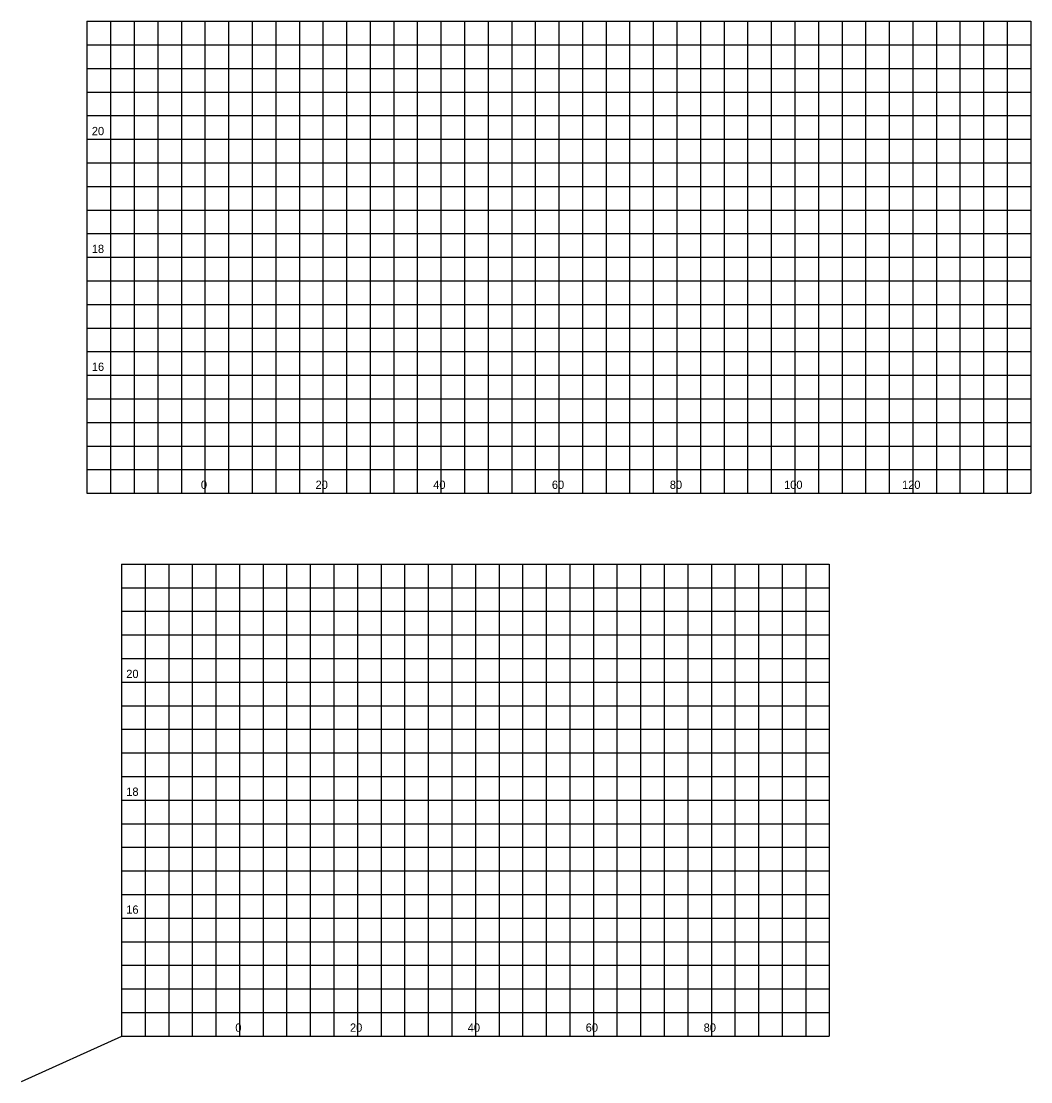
# Model space of a CAD drawing. Extents: x 127723 to 128378, y 21426 to 23736.
# Drawn here: x 128066.4 to 128237.5, y 21431.2 to 21611 of the extents above; entities that cross this region are included whole.
import ezdxf

# ---------------------------------------------------------------- set-up
doc = ezdxf.new("R2010")
doc.units = 0
for name, color, linetype in [('GroundCover', 7, 'Continuous'), ('Miscellaneous0', 7, 'Continuous'), ('SheetBorder_dp', 7, 'Continuous'), ('TextNotes', 7, 'Continuous')]:
    doc.layers.add(name, color=color, linetype=linetype)

msp = doc.modelspace()

# ---------------------------------------------------------------- linework, layer by layer
at = {"layer": 'Miscellaneous0'}
for p, q in [((128081.53, 21610.98), (128081.53, 21530.98)), ((128085.53, 21610.98), (128085.53, 21530.98)), ((128089.53, 21610.98), (128089.53, 21530.98)), ((128093.53, 21610.98), (128093.53, 21530.98)), ((128101.53, 21610.98), (128101.53, 21530.98)), ((128105.53, 21610.98), (128105.53, 21530.98)), ((128109.53, 21610.98), (128109.53, 21530.98)), ((128113.53, 21610.98), (128113.53, 21530.98)), ((128121.53, 21610.98), (128121.53, 21530.98)), ((128125.53, 21610.98), (128125.53, 21530.98)), ((128129.53, 21610.98), (128129.53, 21530.98)), ((128133.53, 21610.98), (128133.53, 21530.98)), ((128141.53, 21610.98), (128141.53, 21530.98)), ((128145.53, 21610.98), (128145.53, 21530.98)), ((128149.53, 21610.98), (128149.53, 21530.98)), ((128153.53, 21610.98), (128153.53, 21530.98)), ((128161.53, 21610.98), (128161.53, 21530.98)), ((128165.53, 21610.98), (128165.53, 21530.98)), ((128169.53, 21610.98), (128169.53, 21530.98)), ((128173.53, 21610.98), (128173.53, 21530.98)), ((128181.53, 21610.98), (128181.53, 21530.98)), ((128185.53, 21610.98), (128185.53, 21530.98)), ((128189.53, 21610.98), (128189.53, 21530.98)), ((128193.53, 21610.98), (128193.53, 21530.98)), ((128201.53, 21610.98), (128201.53, 21530.98)), ((128205.53, 21610.98), (128205.53, 21530.98)), ((128209.53, 21610.98), (128209.53, 21530.98)), ((128213.53, 21610.98), (128213.53, 21530.98)), ((128221.53, 21610.98), (128221.53, 21530.98)), ((128225.53, 21610.98), (128225.53, 21530.98)), ((128229.53, 21610.98), (128229.53, 21530.98)), ((128233.53, 21610.98), (128233.53, 21530.98)), ((128077.53, 21606.98), (128157.53, 21606.98)), ((128157.53, 21606.98), (128237.53, 21606.98)), ((128077.53, 21602.98), (128157.53, 21602.98)), ((128157.53, 21602.98), (128237.53, 21602.98)), ((128077.53, 21598.98), (128157.53, 21598.98)), ((128157.53, 21598.98), (128237.53, 21598.98)), ((128077.53, 21594.98), (128157.53, 21594.98)), ((128157.53, 21594.98), (128237.53, 21594.98)), ((128077.53, 21586.98), (128157.53, 21586.98)), ((128157.53, 21586.98), (128237.53, 21586.98)), ((128077.53, 21582.98), (128157.53, 21582.98)), ((128157.53, 21582.98), (128237.53, 21582.98)), ((128077.53, 21578.98), (128157.53, 21578.98)), ((128157.53, 21578.98), (128237.53, 21578.98)), ((128077.53, 21574.98), (128157.53, 21574.98)), ((128157.53, 21574.98), (128237.53, 21574.98)), ((128077.53, 21566.98), (128157.53, 21566.98)), ((128157.53, 21566.98), (128237.53, 21566.98)), ((128077.53, 21562.98), (128157.53, 21562.98)), ((128157.53, 21562.98), (128237.53, 21562.98)), ((128077.53, 21558.98), (128157.53, 21558.98)), ((128157.53, 21558.98), (128237.53, 21558.98)), ((128077.53, 21554.98), (128157.53, 21554.98)), ((128157.53, 21554.98), (128237.53, 21554.98)), ((128077.53, 21546.98), (128157.53, 21546.98)), ((128157.53, 21546.98), (128237.53, 21546.98)), ((128077.53, 21542.98), (128157.53, 21542.98)), ((128157.53, 21542.98), (128237.53, 21542.98)), ((128077.53, 21538.98), (128157.53, 21538.98)), ((128157.53, 21538.98), (128237.53, 21538.98)), ((128077.53, 21534.98), (128157.53, 21534.98)), ((128157.53, 21534.98), (128237.53, 21534.98)), ((128087.38, 21518.98), (128087.38, 21438.98)), ((128091.38, 21518.98), (128091.38, 21438.98)), ((128095.38, 21518.98), (128095.38, 21438.98)), ((128099.38, 21518.98), (128099.38, 21438.98)), ((128107.38, 21518.98), (128107.38, 21438.98)), ((128111.38, 21518.98), (128111.38, 21438.98)), ((128115.38, 21518.98), (128115.38, 21438.98)), ((128119.38, 21518.98), (128119.38, 21438.98)), ((128127.38, 21518.98), (128127.38, 21438.98)), ((128131.38, 21518.98), (128131.38, 21438.98)), ((128135.38, 21518.98), (128135.38, 21438.98)), ((128139.38, 21518.98), (128139.38, 21438.98)), ((128147.38, 21518.98), (128147.38, 21438.98)), ((128151.38, 21518.98), (128151.38, 21438.98)), ((128155.38, 21518.98), (128155.38, 21438.98)), ((128159.38, 21518.98), (128159.38, 21438.98)), ((128167.38, 21518.98), (128167.38, 21438.98)), ((128171.38, 21518.98), (128171.38, 21438.98)), ((128175.38, 21518.98), (128175.38, 21438.98)), ((128179.38, 21518.98), (128179.38, 21438.98)), ((128187.38, 21518.98), (128187.38, 21438.98)), ((128191.38, 21518.98), (128191.38, 21438.98)), ((128195.38, 21518.98), (128195.38, 21438.98)), ((128199.38, 21518.98), (128199.38, 21438.98)), ((128083.38, 21514.98), (128203.38, 21514.98)), ((128083.38, 21510.98), (128203.38, 21510.98)), ((128083.38, 21506.98), (128203.38, 21506.98)), ((128083.38, 21502.98), (128203.38, 21502.98)), ((128083.38, 21494.98), (128203.38, 21494.98)), ((128083.38, 21490.98), (128203.38, 21490.98)), ((128083.38, 21486.98), (128203.38, 21486.98)), ((128083.38, 21482.98), (128203.38, 21482.98)), ((128083.38, 21474.98), (128203.38, 21474.98)), ((128083.38, 21470.98), (128203.38, 21470.98)), ((128083.38, 21466.98), (128203.38, 21466.98)), ((128083.38, 21462.98), (128203.38, 21462.98)), ((128083.38, 21454.98), (128203.38, 21454.98)), ((128083.38, 21450.98), (128203.38, 21450.98)), ((128083.38, 21446.98), (128203.38, 21446.98)), ((128083.38, 21442.98), (128203.38, 21442.98))]:
    msp.add_line(p, q, dxfattribs=at)
at = {"layer": 'SheetBorder_dp'}
for p, q in [((128077.53, 21610.98), (128157.53, 21610.98)), ((128077.53, 21610.98), (128077.53, 21530.98)), ((128097.53, 21610.98), (128097.53, 21550.98)), ((128097.53, 21610.98), (128097.53, 21530.98)), ((128117.53, 21610.98), (128117.53, 21530.98)), ((128137.53, 21610.98), (128137.53, 21530.98)), ((128157.53, 21610.98), (128157.53, 21530.98)), ((128157.53, 21610.98), (128237.53, 21610.98)), ((128177.53, 21610.98), (128177.53, 21550.98)), ((128177.53, 21610.98), (128177.53, 21530.98)), ((128197.53, 21610.98), (128197.53, 21530.98)), ((128217.53, 21610.98), (128217.53, 21530.98)), ((128237.53, 21610.98), (128237.53, 21530.98)), ((128077.53, 21590.98), (128157.53, 21590.98)), ((128157.53, 21590.98), (128237.53, 21590.98)), ((128077.53, 21570.98), (128157.53, 21570.98)), ((128157.53, 21570.98), (128237.53, 21570.98)), ((128077.53, 21550.98), (128157.53, 21550.98)), ((128077.53, 21550.98), (128157.53, 21550.98)), ((128157.53, 21550.98), (128237.53, 21550.98)), ((128157.53, 21550.98), (128237.53, 21550.98)), ((128077.53, 21530.98), (128157.53, 21530.98)), ((128157.53, 21530.98), (128237.53, 21530.98)), ((128083.38, 21518.98), (128203.38, 21518.98)), ((128083.38, 21518.98), (128083.38, 21438.98)), ((128103.38, 21518.98), (128103.38, 21458.98)), ((128103.38, 21518.98), (128103.38, 21438.98)), ((128123.38, 21518.98), (128123.38, 21438.98)), ((128143.38, 21518.98), (128143.38, 21438.98)), ((128163.38, 21518.98), (128163.38, 21438.98)), ((128183.38, 21518.98), (128183.38, 21438.98)), ((128203.38, 21518.98), (128203.38, 21438.98)), ((128083.38, 21498.98), (128203.38, 21498.98)), ((128083.38, 21478.98), (128203.38, 21478.98)), ((128083.38, 21458.98), (128163.38, 21458.98)), ((128083.38, 21458.98), (128203.38, 21458.98)), ((128083.38, 21438.98), (128203.38, 21438.98))]:
    msp.add_line(p, q, dxfattribs=at)
at = {"layer": 'TextNotes'}
msp.add_line((128083.38, 21438.9), (128066.38, 21431.24), dxfattribs=at)

# ---------------------------------------------------------------- texts
at = {"layer": 'GroundCover'}
for s, p in [('20', (128078.35, 21591.67)), ('18', (128078.35, 21571.7)), ('16', (128078.35, 21551.72)), ('0', (128096.84, 21531.72)), ('20', (128116.28, 21531.72)), ('40', (128136.23, 21531.72)), ('60', (128156.34, 21531.72)), ('80', (128176.34, 21531.72)), ('100', (128195.71, 21531.72)), ('120', (128215.71, 21531.72)), ('20', (128084.19, 21499.67)), ('18', (128084.19, 21479.7)), ('16', (128084.19, 21459.72)), ('0', (128102.68, 21439.72)), ('20', (128122.12, 21439.72)), ('40', (128142.08, 21439.72)), ('60', (128162.08, 21439.72)), ('80', (128182.08, 21439.72))]:
    msp.add_text(s, height=1.4, dxfattribs=at).set_placement(p)

doc.saveas('drawing.dxf')
